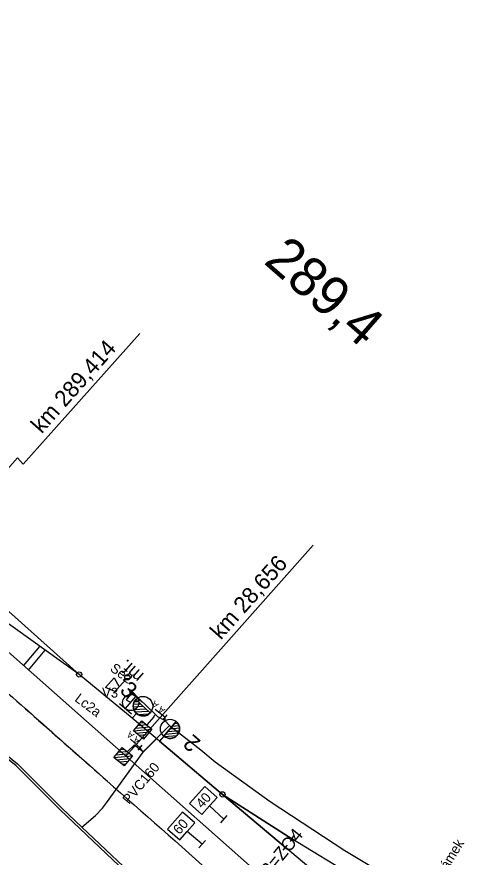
# Model space of a CAD drawing. Extents: x -496570 to -495506, y -1089156 to -1088046.
# Drawn here: x -495811 to -495738.9, y -1088785.1 to -1088656.4 of the extents above; entities that cross this region are included whole.
import ezdxf

# ---------------------------------------------------------------- set-up
doc = ezdxf.new("R2010")
doc.units = 0
for name, color, linetype in [('11', 7, 'Continuous'), ('14', 7, 'Continuous'), ('15', 7, 'Continuous'), ('20', 7, 'Continuous'), ('27', 7, 'Continuous'), ('4', 7, 'Continuous'), ('54', 7, 'Continuous'), ('PŘÍSTUPOVÉ_CESTY', 7, 'Continuous'), ('PŮVODNÍ_NÁVRH', 7, 'Continuous')]:
    doc.layers.add(name, color=color, linetype=linetype)

msp = doc.modelspace()

# ---------------------------------------------------------------- linework, layer by layer
at = {"layer": '11'}
for points in [[(-495809.946, -1088755.786), (-495807.484, -1088752.822)], [(-495809.193, -1088756.446), (-495806.665, -1088753.405)]]:
    msp.add_lwpolyline(points, dxfattribs=at)
at = {"layer": '14'}
for p, q in [((-495781.344, -1088773.877), (-495781.344, -1088773.877)), ((-495768.855, -1088782.288), (-495779.5, -1088775.496)), ((-495752.234, -1088792.438), (-495768.855, -1088782.288))]:
    msp.add_line(p, q, dxfattribs=at)
for points in [[(-495824.02, -1088743.323), (-495815.059, -1088751.264), (-495794.086, -1088769.814), (-495773.102, -1088788.384), (-495756.038, -1088803.462), (-495743.611, -1088814.438)], [(-495597.746, -1088928.689), (-495606.602, -1088921.27), (-495628.038, -1088903.237), (-495662.023, -1088874.554), (-495695.238, -1088846.561), (-495728.41, -1088818.593), (-495747.734, -1088802.274), (-495769.843, -1088783.642), (-495779.5, -1088775.496), (-495789.139, -1088767.364), (-495793.346, -1088763.837)]]:
    msp.add_lwpolyline(points, dxfattribs=at)
for centre, major_axis, ratio, start_param, end_param in [((-493580.338, -1086191.204), (6302.474, -5605.928), 0.4034223, 4.7161395, 4.7194844), ((-486260.704, -1078050.473), (-12285.28, 10646.007), 0.8827289, 1.5584059, 1.5611507)]:
    msp.add_ellipse(centre, major_axis=major_axis, ratio=ratio, start_param=start_param, end_param=end_param, dxfattribs=at)
at = {"layer": '15'}
for p, q in [((-495793.67, -1088759.692), (-495791.812, -1088761.31)), ((-495795.288, -1088761.55), (-495793.43, -1088763.168)), ((-495794.359, -1088762.359), (-495792.741, -1088760.501)), ((-495793.123, -1088765.758), (-495790.308, -1088765.486)), ((-495792.786, -1088765.349), (-495790.717, -1088765.149)), ((-495792.449, -1088764.939), (-495791.127, -1088764.811)), ((-495792.112, -1088764.53), (-495791.536, -1088764.474)), ((-495792.714, -1088766.095), (-495790.645, -1088765.895)), ((-495792.305, -1088766.432), (-495790.983, -1088766.305)), ((-495791.895, -1088766.769), (-495791.32, -1088766.714)), ((-495795.768, -1088769.434), (-495793.698, -1088769.24)), ((-495795.429, -1088769.025), (-495794.107, -1088768.901)), ((-495795.091, -1088768.617), (-495794.515, -1088768.563)), ((-495796.106, -1088769.843), (-495793.29, -1088769.578)), ((-495795.698, -1088770.181), (-495793.628, -1088769.986)), ((-495795.289, -1088770.519), (-495793.967, -1088770.395)), ((-495794.88, -1088770.857), (-495794.305, -1088770.803))]:
    msp.add_line(p, q, dxfattribs=at)
for points in [[(-495791.852, -1088764.214), (-495790.308, -1088765.486), (-495791.58, -1088767.029), (-495793.123, -1088765.758)], [(-495791.852, -1088764.214), (-495790.308, -1088765.486), (-495791.58, -1088767.029), (-495793.123, -1088765.758)], [(-495794.83, -1088768.302), (-495793.29, -1088769.578), (-495794.565, -1088771.118), (-495796.106, -1088769.843)], [(-495794.83, -1088768.302), (-495793.29, -1088769.578), (-495794.565, -1088771.118), (-495796.106, -1088769.843)]]:
    msp.add_lwpolyline(points, close=True, dxfattribs=at)
for points in [[(-495791.852, -1088764.214), (-495790.308, -1088765.486), (-495791.58, -1088767.029), (-495793.123, -1088765.758), (-495791.852, -1088764.214)], [(-495791.852, -1088764.214), (-495790.308, -1088765.486), (-495791.58, -1088767.029), (-495793.123, -1088765.758), (-495791.852, -1088764.214)], [(-495794.83, -1088768.302), (-495793.29, -1088769.578), (-495794.565, -1088771.118), (-495796.106, -1088769.843), (-495794.83, -1088768.302)], [(-495794.83, -1088768.302), (-495793.29, -1088769.578), (-495794.565, -1088771.118), (-495796.106, -1088769.843), (-495794.83, -1088768.302)]]:
    msp.add_lwpolyline(points, dxfattribs=at)
msp.add_circle((-495793.548, -1088761.425), 1.232, dxfattribs=at)
at = {"layer": '20'}
for p, q in [((-495789.792, -1088762.415), (-495788.26, -1088763.67)), ((-495788.577, -1088764.057), (-495787.943, -1088763.283)), ((-495793.6, -1088767.048), (-495792.1, -1088768.34)), ((-495792.426, -1088768.719), (-495791.774, -1088767.961))]:
    msp.add_line(p, q, dxfattribs=at)
at = {"layer": '27'}
for p, q in [((-495810.019, -1088724.923), (-495792.165, -1088704.887)), ((-495829.435, -1088744.846), (-495810.865, -1088723.912)), ((-495810.865, -1088723.912), (-495810.019, -1088724.923)), ((-495794.281, -1088769.662), (-495765.578, -1088737.304)), ((-495801.447, -1088757.122), (-495814.907, -1088747.535)), ((-495793.134, -1088761.674), (-495792.071, -1088761.62)), ((-495792.984, -1088761.266), (-495792.49, -1088761.241)), ((-495790.557, -1088762.987), (-495792.783, -1088760.976)), ((-495792.783, -1088760.976), (-495790.557, -1088762.987)), ((-495793.163, -1088762.076), (-495791.651, -1088761.999)), ((-495793.084, -1088762.473), (-495791.231, -1088762.379)), ((-495792.88, -1088762.863), (-495790.812, -1088762.758)), ((-495792.676, -1088763.095), (-495793.346, -1088763.837)), ((-495792.479, -1088763.243), (-495790.74, -1088763.155)), ((-495788.478, -1088766.576), (-495786.59, -1088764.339)), ((-495786.59, -1088764.339), (-495788.477, -1088766.576)), ((-495787.519, -1088765.441), (-495786.08, -1088765.318)), ((-495787.177, -1088765.035), (-495786.165, -1088764.949)), ((-495786.835, -1088764.629), (-495786.36, -1088764.59)), ((-495788.479, -1088766.576), (-495789.139, -1088767.364)), ((-495788.477, -1088766.576), (-495788.478, -1088766.576)), ((-495788.386, -1088766.643), (-495786.494, -1088766.482)), ((-495788.203, -1088766.25), (-495786.213, -1088766.082)), ((-495787.862, -1088765.846), (-495786.092, -1088765.695)), ((-495768.586, -1088781.867), (-495769.124, -1088782.709)), ((-495770.175, -1088784.016), (-495769.511, -1088783.268))]:
    msp.add_line(p, q, dxfattribs=at)
for points in [[(-495793.346, -1088763.837), (-495801.447, -1088757.122), (-495813.723, -1088746.171)], [(-495789.139, -1088767.364), (-495779.5, -1088775.496), (-495769.843, -1088783.642)], [(-495779.5, -1088775.496), (-495768.855, -1088782.288)]]:
    msp.add_lwpolyline(points, dxfattribs=at)
for centre, radius in [((-495801.447, -1088757.122), 0.4), ((-495791.67, -1088761.982), 1.5), ((-495787.527, -1088765.452), 1.462), ((-495779.5, -1088775.496), 0.4)]:
    msp.add_circle(centre, radius, dxfattribs=at)
for centre, radius, start, end in [((-495791.67, -1088761.982), 1.5, 137.90518, 317.90518), ((-495787.534, -1088765.457), 1.464, 229.86672, 49.82757)]:
    msp.add_arc(centre, radius, start, end, dxfattribs=at)
at = {"layer": '4'}
for p, q in [((-495779.765, -1088779.832), (-495778.763, -1088778.716)), ((-495783.093, -1088783.685), (-495782.113, -1088782.549))]:
    msp.add_line(p, q, dxfattribs=at)
for points in [[(-495779.264, -1088779.274), (-495781.495, -1088777.269), (-495780.326, -1088775.967), (-495782.185, -1088774.296), (-495784.524, -1088776.899), (-495782.665, -1088778.57), (-495781.495, -1088777.269)], [(-495782.603, -1088783.117), (-495784.874, -1088781.157), (-495783.73, -1088779.832), (-495785.623, -1088778.198), (-495787.91, -1088780.847), (-495786.017, -1088782.481), (-495784.874, -1088781.157)]]:
    msp.add_lwpolyline(points, dxfattribs=at)
at = {"layer": '54'}
msp.add_line((-495791.62, -1088769.02), (-495792.1, -1088768.34), dxfattribs=at)
for points in [[(-495791.286, -1088790.273), (-495804.369, -1088777.872), (-495811.106, -1088771.12), (-495824.244, -1088760.551), (-495840.179, -1088747.357), (-495841.548, -1088746.404), (-495845, -1088746.917), (-495854.533, -1088753.524), (-495860.828, -1088746.983), (-495869.129, -1088742.363), (-495894.734, -1088714.89), (-495907.733, -1088698.276), (-495926.154, -1088680.584), (-495936.743, -1088670.436), (-495952.112, -1088656.757)], [(-495951.647, -1088656.374), (-495945.893, -1088661.488), (-495936.346, -1088669.973), (-495925.773, -1088680.163), (-495906.553, -1088698.536), (-495896.884, -1088711.088), (-495893.995, -1088714.839), (-495868.155, -1088742.416), (-495860.018, -1088746.657), (-495854.533, -1088753.524), (-495845, -1088746.917), (-495841.548, -1088746.404), (-495840.19, -1088746.67), (-495839.894, -1088747.064), (-495839.734, -1088747.366), (-495839.482, -1088747.646), (-495839.66, -1088747.957), (-495839.679, -1088748.032), (-495838.294, -1088748.402), (-495823.909, -1088760.307), (-495810.91, -1088770.79), (-495804.093, -1088777.585), (-495801.02, -1088780.504), (-495790.99, -1088790.03)], [(-495788.34, -1088764.2), (-495789.37, -1088763.59), (-495789.74, -1088763.28), (-495792.26, -1088760.84), (-495793.41, -1088759.61), (-495793.36, -1088759.92), (-495794.22, -1088761.02), (-495793.55, -1088761.43)], [(-495789.74, -1088763.28), (-495789.99, -1088763.49), (-495790, -1088763.62), (-495791.08, -1088764.85)], [(-495787.63, -1088764.94), (-495788.34, -1088764.2), (-495788.26, -1088764.01), (-495788.29, -1088763.64)], [(-495801.02, -1088780.504), (-495798.92, -1088778.73), (-495797.85, -1088777.59), (-495797.28, -1088776.77), (-495791.62, -1088769.02), (-495791.36, -1088768.71), (-495787.63, -1088764.94), (-495782.78, -1088768.65), (-495780.586, -1088770.513), (-495772.205, -1088776.561), (-495760.742, -1088784.104), (-495747.832, -1088791.845), (-495744.126, -1088794.068), (-495736.431, -1088799.383), (-495727.765, -1088805.834), (-495719.117, -1088812.973), (-495707.178, -1088822.151), (-495697.976, -1088829.465), (-495688.794, -1088836.279), (-495680.237, -1088841.671), (-495677.295, -1088842.948), (-495661.742, -1088852.793), (-495655.07, -1088855.99)], [(-495794.06, -1088768.94), (-495793.07, -1088768), (-495792.99, -1088767.91), (-495792.01, -1088768.69), (-495791.62, -1088769.02)]]:
    msp.add_lwpolyline(points, dxfattribs=at)
at = {"layer": 'PŘÍSTUPOVÉ_CESTY'}
for p, q in [((-495797.418, -1088759.122), (-495796.092, -1088757.625)), ((-495796.092, -1088757.625), (-495795.301, -1088758.994)), ((-495793.735, -1088757.331), (-495794.416, -1088757.372)), ((-495793.703, -1088757.73), (-495794.397, -1088757.772)), ((-495796.163, -1088759.967), (-495794.311, -1088757.873)), ((-495795.964, -1088759.743), (-495797.418, -1088759.122))]:
    msp.add_line(p, q, dxfattribs=at)
msp.add_circle((-495794.063, -1088757.558), 0.401, dxfattribs=at)
msp.add_circle((-495794.063, -1088757.558), 0.401, dxfattribs=at)
at = {"layer": 'PŮVODNÍ_NÁVRH'}
msp.add_lwpolyline([(-495797.85, -1088777.59), (-495797.28, -1088776.77), (-495791.62, -1088769.02), (-495787.63, -1088764.94)], dxfattribs=at)

# ---------------------------------------------------------------- texts
at = {"layer": '11'}
msp.add_text('289,4', height=6, rotation=318.94379, dxfattribs=at).set_placement((-495773.33, -1088694.046))
at = {"layer": '14'}
msp.add_text('KO3=ZO4', height=2, rotation=50.72946, dxfattribs=at).set_placement((-495774.669, -1088791.122))
at = {"layer": '15'}
msp.add_text('V3', height=1.5, dxfattribs=at).set_placement((-495797.933, -1088760.663))
at = {"layer": '20'}
for s, height, rotation, p in [('Se2', 1.5, 323.04383, (-495796.83, -1088756.453)), ('Lc2a', 1.5, 323.04383, (-495802.248, -1088761.101)), ('  A A', 1, 140.67971, (-495787.61, -1088762.944)), ('  A A', 1, 139.25058, (-495791.432, -1088767.63))]:
    msp.add_text(s, height=height, rotation=rotation, dxfattribs=at).set_placement(p)
at = {"layer": '27'}
for s, rotation, p in [('km 289,414', 48.42518, (-495807.191, -1088720.344)), ('km 28,656', 48.42518, (-495779.748, -1088751.941)), ('3', 316.1844, (-495795.364, -1088759.713)), ('2', 138.47383, (-495782.674, -1088767.364))]:
    msp.add_text(s, height=2.5, rotation=rotation, dxfattribs=at).set_placement(p)
at = {"layer": '4'}
for s, p in [('40', (-495782.588, -1088777.727)), ('60', (-495786.085, -1088781.747))]:
    msp.add_text(s, height=1.5, rotation=48.52464, dxfattribs=at).set_placement(p)
at = {"layer": '54'}
for s, rotation, p in [('PVC160', 50, (-495793.806, -1088777.121)), ('el. zámek', 58.47782, (-495746.915, -1088790.271))]:
    msp.add_text(s, height=1.5, rotation=rotation, dxfattribs=at).set_placement(p)
at = {"layer": 'PŘÍSTUPOVÉ_CESTY'}
msp.add_text('mf.', height=2, rotation=138.45644, dxfattribs=at).set_placement((-495791.4, -1088757.107))

doc.saveas('drawing.dxf')
